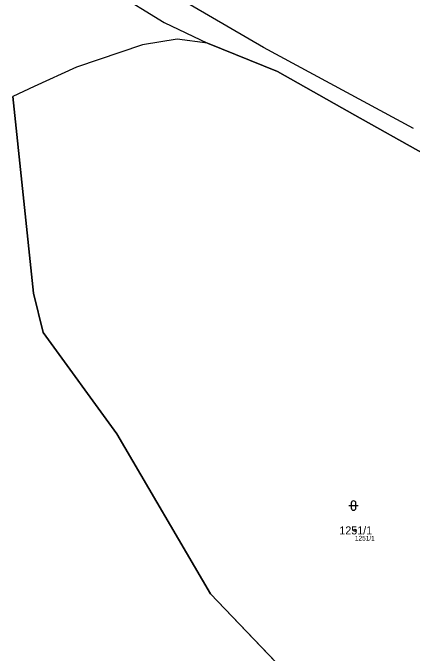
# Model space of a CAD drawing. Extents: x -781091 to -780384, y -1093010 to -1092030.
# Drawn here: x -780920.9 to -780836.1, y -1092393.7 to -1092257.6 of the extents above; entities that cross this region are included whole.
import ezdxf

# ---------------------------------------------------------------- set-up
doc = ezdxf.new("R2010")
doc.units = 0
for name, color, linetype in [('Vrstva 1', 7, 'Continuous'), ('Vrstva 2', 7, 'Continuous'), ('Vrstva 3', 7, 'Continuous'), ('Vrstva 50', 7, 'Continuous'), ('Vrstva 51', 7, 'Continuous')]:
    doc.layers.add(name, color=color, linetype=linetype)

msp = doc.modelspace()

# ---------------------------------------------------------------- linework, layer by layer
at = {"layer": 'Vrstva 1'}
msp.add_line((-780878.89, -1092381.04), (-780843.02, -1092418.61), dxfattribs=at)
for points in [[(-780879.57, -1092264.03), (-780864.65, -1092270.09), (-780848.28, -1092279.36), (-780833.6, -1092287.57), (-780817.83, -1092293.86), (-780800.49, -1092299.43), (-780792.33, -1092300.67), (-780786.97, -1092303.35), (-780783.1, -1092308.11), (-780781.85, -1092315.45), (-780783.01, -1092320.54), (-780789.1, -1092328.24), (-780798.01, -1092342.06), (-780806.54, -1092358.44), (-780819.19, -1092385.38), (-780823.21, -1092395.87), (-780827.6, -1092411.94), (-780833.73, -1092439.91), (-780840.39, -1092483.26), (-780842.9, -1092496.39)], [(-780914.4, -1092325.54), (-780916.5, -1092317.18), (-780920.87, -1092275.39)], [(-780878.89, -1092381.04), (-780898.79, -1092347.04), (-780914.4, -1092325.54)]]:
    msp.add_lwpolyline(points, dxfattribs=at)
at = {"layer": 'Vrstva 3'}
for p, q in [((-780849.051, -1092361.791), (-780849.051, -1092362.792)), ((-780848.049, -1092362.792), (-780848.049, -1092361.791)), ((-780849.551, -1092362.291), (-780847.549, -1092362.291))]:
    msp.add_line(p, q, dxfattribs=at)
for centre, start, end in [((-780848.55, -1092361.7909), 0, 180), ((-780848.55, -1092362.7909), 180, 359.9878861)]:
    msp.add_arc(centre, 0.5, start, end, dxfattribs=at)
at = {"layer": 'Vrstva 50'}
msp.add_circle((-780848.25, -1092367.56994), 0.25, dxfattribs=at)
at = {"layer": 'Vrstva 51'}
for points in [[(-780835.81, -1092282.14), (-780867.63, -1092264.99), (-780913.54, -1092238.2)], [(-780899.58, -1092252.88), (-780888.73, -1092259.62), (-780879.57, -1092264.03), (-780864.65, -1092270.09), (-780848.28, -1092279.36), (-780833.6, -1092287.57)], [(-780833.6, -1092287.57), (-780848.28, -1092279.36), (-780864.65, -1092270.09), (-780879.57, -1092264.03), (-780885.99, -1092263.19), (-780893.35, -1092264.41), (-780907.35, -1092269.12), (-780916.36, -1092273.25), (-780920.87, -1092275.39), (-780916.5, -1092317.18), (-780914.4, -1092325.54), (-780898.79, -1092347.04), (-780878.89, -1092381.04), (-780843.02, -1092418.61), (-780846.85, -1092429.08), (-780845.02, -1092429.42), (-780840.27, -1092432.48), (-780836.38, -1092436.9), (-780838.49, -1092453.8), (-780841.33, -1092476.47), (-780843.75, -1092495.8), (-780842.9, -1092496.39), (-780840.39, -1092483.26), (-780833.73, -1092439.91)]]:
    msp.add_lwpolyline(points, dxfattribs=at)

# ---------------------------------------------------------------- texts
at = {"layer": 'Vrstva 2'}
msp.add_text('1251/1', height=1.699998, dxfattribs=at).set_placement((-780851.555, -1092368.42))
at = {"layer": 'Vrstva 50'}
msp.add_text('1251/1', height=0.999996, dxfattribs=at).set_placement((-780848.25, -1092369.726))

doc.saveas('drawing.dxf')
